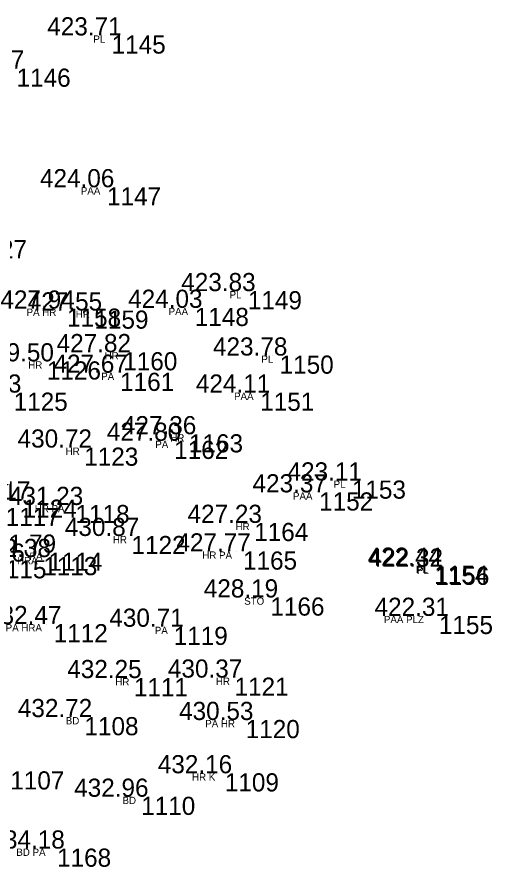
# Model space of a CAD drawing. Extents: x -639390 to -639075, y -1138747 to -1138358.
# Drawn here: x -639094.29 to -639074.7, y -1138734.42 to -1138699.32 of the extents above; entities that cross this region are included whole.
import ezdxf

# ---------------------------------------------------------------- set-up
doc = ezdxf.new("R2010")
doc.units = 0
for name, color, linetype in [('Vrstva 11', 7, 'Continuous'), ('Vrstva 12', 7, 'Continuous'), ('Vrstva 13', 7, 'Continuous'), ('Vrstva 57', 7, 'Continuous')]:
    doc.layers.add(name, color=color, linetype=linetype)

msp = doc.modelspace()

# ---------------------------------------------------------------- linework, layer by layer
at = {"layer": 'Vrstva 11'}
for p, q in [((-639090.67, -1138700.08), (-639090.67, -1138700.08)), ((-639090.86, -1138706.35), (-639090.86, -1138706.35)), ((-639085.05, -1138710.64), (-639085.05, -1138710.64)), ((-639092.51, -1138711.36), (-639092.51, -1138711.36)), ((-639091.38, -1138711.44), (-639091.38, -1138711.44)), ((-639087.24, -1138711.33), (-639087.24, -1138711.33)), ((-639090.19, -1138713.16), (-639090.19, -1138713.16)), ((-639083.74, -1138713.3), (-639083.74, -1138713.3)), ((-639093.34, -1138713.54), (-639093.34, -1138713.54)), ((-639090.32, -1138714.01), (-639090.32, -1138714.01)), ((-639084.54, -1138714.83), (-639084.54, -1138714.83)), ((-639088.09, -1138716.82), (-639088.09, -1138716.82)), ((-639087.48, -1138716.55), (-639087.48, -1138716.55)), ((-639091.8, -1138717.1), (-639091.8, -1138717.1)), ((-639080.76, -1138718.46), (-639080.76, -1138718.46)), ((-639082.11, -1138718.95), (-639082.11, -1138718.95)), ((-639092.16, -1138719.47), (-639092.16, -1138719.47)), ((-639084.79, -1138720.21), (-639084.79, -1138720.21)), ((-639089.85, -1138720.75), (-639089.85, -1138720.75)), ((-639085.25, -1138721.39), (-639085.25, -1138721.39)), ((-639093.49, -1138721.62), (-639093.49, -1138721.62)), ((-639093.28, -1138721.44), (-639093.28, -1138721.44)), ((-639077.36, -1138721.98), (-639077.36, -1138721.98)), ((-639077.32, -1138722.02), (-639077.32, -1138722.02)), ((-639084.12, -1138723.29), (-639084.12, -1138723.29)), ((-639077.17, -1138724.05), (-639077.17, -1138724.05)), ((-639093.06, -1138724.39), (-639093.06, -1138724.39)), ((-639088.11, -1138724.5), (-639088.11, -1138724.5)), ((-639089.75, -1138726.62), (-639089.75, -1138726.62)), ((-639085.6, -1138726.6), (-639085.6, -1138726.6)), ((-639091.79, -1138728.23), (-639091.79, -1138728.23)), ((-639085.14, -1138728.35), (-639085.14, -1138728.35)), ((-639086, -1138730.55), (-639086, -1138730.55)), ((-639089.45, -1138731.52), (-639089.45, -1138731.52)), ((-639092.92, -1138733.66), (-639092.92, -1138733.66))]:
    msp.add_line(p, q, dxfattribs=at)

# ---------------------------------------------------------------- texts
at = {"layer": 'Vrstva 12'}
for s, p in [('423.71 ', (-639093.045, -1138700.08)), ('424.17 ', (-639097.059, -1138701.45)), ('424.06 ', (-639093.346, -1138706.35)), ('423.83 ', (-639087.519, -1138710.64)), ('427.94 ', (-639094.979, -1138711.36)), ('427.55 ', (-639093.85, -1138711.44)), ('424.03 ', (-639089.709, -1138711.33)), ('427.82 ', (-639092.659, -1138713.16)), ('423.78 ', (-639086.209, -1138713.3)), ('429.50 ', (-639095.839, -1138713.54)), ('427.67 ', (-639092.789, -1138714.01)), ('429.93 ', (-639097.179, -1138714.83)), ('424.11 ', (-639086.915, -1138714.83)), ('427.36 ', (-639089.966, -1138716.55)), ('427.80 ', (-639090.589, -1138716.82)), ('430.72 ', (-639094.269, -1138717.1)), ('423.11 ', (-639083.135, -1138718.46)), ('423.37 ', (-639084.579, -1138718.95)), ('431.17 ', (-639096.809, -1138719.25)), ('431.23 ', (-639094.629, -1138719.47)), ('427.23 ', (-639087.259, -1138720.21)), ('430.87 ', (-639092.319, -1138720.75)), ('431.79 ', (-639095.749, -1138721.44)), ('427.77 ', (-639087.719, -1138721.39)), ('432.38 ', (-639095.959, -1138721.62)), ('422.44 ', (-639079.829, -1138721.98)), ('422.32 ', (-639079.789, -1138722.02)), ('428.19 ', (-639086.589, -1138723.29)), ('422.31 ', (-639079.545, -1138724.05)), ('432.47 ', (-639095.529, -1138724.39)), ('430.71 ', (-639090.485, -1138724.5)), ('432.25 ', (-639092.22, -1138726.62)), ('430.37 ', (-639088.069, -1138726.6)), ('432.72 ', (-639094.259, -1138728.23)), ('430.53 ', (-639087.609, -1138728.35)), ('432.16 ', (-639088.486, -1138730.55)), ('432.96 ', (-639091.936, -1138731.52)), ('434.18 ', (-639095.389, -1138733.66))]:
    msp.add_text(s, height=0.75, dxfattribs=at).set_placement(p)
at = {"layer": 'Vrstva 13'}
for s, p in [(' 1145', (-639090.67, -1138700.83)), (' 1146', (-639094.59, -1138702.2)), (' 1147', (-639090.86, -1138707.1)), (' 1127', (-639096.39, -1138709.28)), (' 1149', (-639085.05, -1138711.39)), (' 1158', (-639092.51, -1138712.11)), (' 1159', (-639091.38, -1138712.19)), (' 1148', (-639087.24, -1138712.08)), (' 1160', (-639090.19, -1138713.91)), (' 1150', (-639083.74, -1138714.05)), (' 1126', (-639093.34, -1138714.29)), (' 1161', (-639090.32, -1138714.76)), (' 1125', (-639094.71, -1138715.58)), (' 1151', (-639084.54, -1138715.58)), (' 1162', (-639088.09, -1138717.57)), (' 1163', (-639087.48, -1138717.3)), (' 1123', (-639091.8, -1138717.85)), (' 1153', (-639080.76, -1138719.21)), (' 1152', (-639082.11, -1138719.7)), (' 1124', (-639094.34, -1138720)), (' 1117', (-639095.04, -1138720.34)), (' 1118', (-639092.16, -1138720.22)), (' 1164', (-639084.79, -1138720.96)), (' 1116', (-639096.48, -1138721.81)), (' 1122', (-639089.85, -1138721.5)), (' 1165', (-639085.25, -1138722.14)), (' 1115', (-639095.59, -1138722.5)), (' 1113', (-639093.49, -1138722.37)), (' 1114', (-639093.28, -1138722.19)), (' 1154', (-639077.36, -1138722.73)), (' 1156', (-639077.32, -1138722.77)), (' 1166', (-639084.12, -1138724.04)), (' 1155', (-639077.17, -1138724.8)), (' 1112', (-639093.06, -1138725.14)), (' 1119', (-639088.11, -1138725.25)), (' 1111', (-639089.75, -1138727.37)), (' 1121', (-639085.6, -1138727.35)), (' 1108', (-639091.79, -1138728.98)), (' 1120', (-639085.14, -1138729.1)), (' 1107', (-639094.85, -1138731.22)), (' 1109', (-639086, -1138731.3)), (' 1110', (-639089.45, -1138732.27)), (' 1168', (-639092.92, -1138734.41))]:
    msp.add_text(s, height=0.75, dxfattribs=at).set_placement(p)
at = {"layer": 'Vrstva 57'}
for s, p in [('PL', (-639091.145, -1138700.38)), ('PAA', (-639091.66, -1138706.65)), ('PL', (-639085.525, -1138710.94)), ('PA HR', (-639093.899, -1138711.66)), ('HR', (-639091.869, -1138711.74)), ('PAA', (-639088.04, -1138711.63)), ('HR', (-639090.679, -1138713.46)), ('PL', (-639084.215, -1138713.6)), ('HR', (-639093.829, -1138713.84)), ('PA', (-639090.82, -1138714.31)), ('PAA', (-639085.34, -1138715.13)), ('PA', (-639088.59, -1138717.12)), ('HR', (-639087.969, -1138716.85)), ('HR', (-639092.289, -1138717.4)), ('PL', (-639081.235, -1138718.76)), ('PAA', (-639082.91, -1138719.25)), ('HR PA', (-639093.56, -1138719.77)), ('HR', (-639085.279, -1138720.51)), ('HR', (-639090.339, -1138721.05)), ('HR PA', (-639086.65, -1138721.69)), ('HRA', (-639094.29, -1138721.92)), ('PA', (-639093.78, -1138721.74)), ('PL', (-639077.835, -1138722.28)), ('PL', (-639077.795, -1138722.32)), ('STO', (-639084.921, -1138723.59)), ('PAA PLZ', (-639079.159, -1138724.35)), ('PA HRA', (-639094.76, -1138724.69)), ('PA', (-639088.61, -1138724.8)), ('HR', (-639090.239, -1138726.92)), ('HR', (-639086.089, -1138726.9)), ('BD', (-639092.281, -1138728.53)), ('PA HR', (-639086.529, -1138728.65)), ('HR K', (-639087.075, -1138730.85)), ('BD', (-639089.941, -1138731.82)), ('BD PA', (-639094.32, -1138733.96))]:
    msp.add_text(s, height=0.3, dxfattribs=at).set_placement(p)

doc.saveas('drawing.dxf')
